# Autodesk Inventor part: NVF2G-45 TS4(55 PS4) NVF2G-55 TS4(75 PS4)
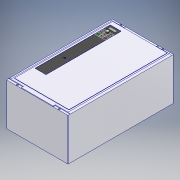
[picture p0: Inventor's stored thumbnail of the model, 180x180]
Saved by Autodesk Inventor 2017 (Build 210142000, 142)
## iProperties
Part Number: NVF2G-45 TS4(55 PS4) NVF2G-55 TS4(75 PS4)
Material: Типовые
Document SubType Name: Modeling
Designer: RSagdiev
Density: 1 g/cm^3
Appearance: По умолчанию
Mass: 52299.3 g
Surface Area: 17585.5 cm^2
Volume: 52299.3 cm^3
Author: RSagdiev
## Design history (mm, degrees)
sketch "Эскиз1"
  geometry: L1 (0, 0)-(44.679, 0) reference; L2 (0, 0)-(0, 56.035) reference; L3 (0, 0)-(603, 0); L4 (603, 0)-(603, 241.6); L5 (603, 241.6)-(0, 241.6); L6 (0, 241.6)-(0, 0)
  constraints: 12 end point, 3 horizontal, 2 parallel, 2 vertical, 1 perpendicular
  dimensions: "d0" = 603 distance of L5.end L4.end; "d1" = 241.6 distance of L4.end L3.end
extrude "Выдавливание1" new body sketch "Эскиз1" stored distance "d2" = 352; taper "d3" = 0 deg
sketch "Эскиз2"
  geometry: L1 (0, 0)-(0, 603) reference; L2 (352, 0)-(352, 603) reference; L3 (0, 603)-(85, 603); L4 (352, 603)-(352, 591); L5 (352, 0)-(267, 0); L6 (0, 0)-(0, 12); L7 (0, 603)-(352, 603) reference; L8 (0, 603)-(85, 603); L9 (85, 603)-(85, 591); L10 (85, 591)-(0, 591); L11 (0, 591)-(0, 603); L12 (352, 603)-(267, 603); L13 (267, 603)-(267, 591); L14 (267, 591)-(352, 591); L15 (352, 591)-(352, 603); L16 (0, 0)-(352, 0) reference; L17 (0, 0)-(85, 0); L18 (85, 0)-(85, 12); L19 (85, 12)-(0, 12); L20 (0, 12)-(0, 0); L21 (352, 0)-(267, 0); L22 (267, 0)-(267, 12); L23 (267, 12)-(352, 12); L24 (352, 12)-(352, 0); L25 (85, 603)-(267, 603); L26 (0, 591)-(0, 603); L27 (267, 603)-(352, 603); L28 (352, 591)-(352, 12); L29 (267, 0)-(85, 0); L30 (352, 12)-(352, 0); L31 (85, 0)-(0, 0); L32 (0, 12)-(0, 591); 1 further point
  constraints: 56 end point, 26 parallel, 13 perpendicular, 7 horizontal
  dimensions: "d4" = 85 distance of L9.end L10.end; "d5" = 12 distance of L3.end L9.end; "d6" = 85 distance of L4.end L13.end; "d7" = 12 distance of L13.end L12.end; "d8" = 85 distance of L6.end L18.end; "d9" = 12 distance of L18.end L17.end; "d10" = 85 distance of L22.end L23.end; "d11" = 12 distance of L5.end L22.end
extrude "Выдавливание2" new body sketch "Эскиз2" distance "d12" = 4; taper "d13" = 0 deg
chamfer "Фаска1" distance "d14" = 4; stored, may be unused: second distance "d15" = 2, angle "d16" = 45 deg
sketch "Эскиз3"
  geometry: L1 (332, 25)-(332, 587); L2 (20, 587)-(332, 587); L3 (20, 587)-(20, 25); L4 (20, 587)-(332, 587); L5 (20, 25)-(332, 25); L6 (85, 599)-(267, 599) reference; L7 (85, 0)-(267, 0) reference; L8 (0, 591)-(0, 12) reference; L9 (352, 12)-(352, 591) reference; 1 further point
  constraints: 11 end point, 2 perpendicular, 1 horizontal
  dimensions: "d160" = 12 distance between parallel lines of L4 L6; "d161" = 25 distance between parallel lines of L7 L5; "d162" = 20 distance between parallel lines of L8 L3 (derived); "d164" = 20 distance between parallel lines of L9 L1
extrude "Выдавливание3" new body sketch "Эскиз3" distance "d17" = 2; taper "d18" = 0 deg
sketch "Эскиз4"
  geometry: L1 (91, 563)-(32, 563); L2 (30, 561)-(30, 135); L3 (32, 133)-(91, 133); L4 (93, 135)-(93, 561); L5 (0, 603)-(352, 603) reference; L6 (0, 591)-(0, 12) reference; A1 r 2 centre (32, 561) between (32, 563) and (30, 561); A2 r 2 centre (91, 561) between (93, 561) and (91, 563); A3 r 2 centre (91, 135) between (91, 133) and (93, 135); A4 r 2 centre (32, 135) between (30, 135) and (32, 133); 6 further points
  constraints: 8 end point, 8 point on circle, 8 tangent, 6 point on line, 4 centre point, 3 equal radius, 2 parallel, 1 horizontal, 1 perpendicular
  dimensions: "d20" = 63 distance of point (93, 133) point (30, 133); "d21" = 430 distance of point (30, 133) point (30, 563); "d24" = 2 radius of A1; "d165" = 40 distance between parallel lines of L5 L1; "d166" = 30 distance between parallel lines of L6 L2
extrude "Выдавливание4" cut sketch "Эскиз4" distance "d25" = 0.6; taper "d26" = 0 deg
sketch "Эскиз5"
  geometry: L1 (0, 603)-(352, 603) reference; L2 (0, 0)-(0, 603) reference; L3 (352, 603)-(352, 0) reference; L4 (0, 0)-(352, 0) reference; C1 r 5 at (56, 597); C2 r 5 at (296, 597); C3 r 5 at (56, 6); C4 r 5 at (296, 6); 1 further point
  constraints: 4 centre point
  dimensions: "d27" = 10 diameter of C1; "d28" = 6 distance from line of C1.centre L1; "d30" = 10 diameter of C2; "d31" = 6 distance from line of C2.centre L1; "d33" = 10 diameter of C3; "d34" = 6 distance from line of L4 C3.centre; "d36" = 10 diameter of C4; "d38" = 6 distance from line of C4.centre L4; "d169" = 240 distance of C1.centre C2.centre; "d170" = 56 distance from line of L3 C2.centre; "d172" = 240 distance of C4.centre C3.centre (derived); "d173" = 56 distance from line of L3 C4.centre (derived); "d202" = 56 distance from line of L2 C1.centre (derived)
extrude "Выдавливание5" cut sketch "Эскиз5" stored distance "d39" = 0.6; taper "d40" = 0 deg
sketch "Эскиз6"
  geometry: L1 (30, 472)-(30, 528); L2 (91, 470)-(32, 470); L3 (93, 561)-(93, 528); L4 (32, 563)-(91, 563); L5 (30, 472)-(30, 561); L6 (30, 528)-(93, 528); L7 (93, 561)-(93, 528); L8 (30, 528)-(30, 561); L9 (93, 528)-(93, 472); L10 (43.5, 539)-(79.5, 539); L11 (81.5, 541)-(81.5, 551); L12 (79.5, 553)-(43.5, 553); L13 (41.5, 551)-(41.5, 541); L14 (41.5, 539)-(81.5, 553); L15 (81.5, 539)-(41.5, 553); L16 (61.5, 516.5)-(61.5, 481.857); L17 (53.25, 516.5)-(53.25, 481.857); L18 (69.75, 481.857)-(69.75, 516.5); L19 (47, 523)-(36, 523); L20 (35, 522)-(35, 511); L21 (36, 510)-(47, 510); L22 (48, 511)-(48, 522); L23 (48, 523)-(35, 510); L24 (35, 523)-(48, 510); L25 (81.5, 541)-(81.5, 476.5); L26 (41.5, 516.5)-(88.409, 516.5); L27 (39.654, 499.179)-(85.729, 499.179); L28 (39.654, 481.857)-(84.963, 481.857); L29 (88, 511)-(88, 522); L30 (76, 510)-(87, 510); L31 (88, 523)-(75, 510); L32 (75, 523)-(88, 510); L33 (75, 522)-(75, 511); L34 (87, 523)-(76, 523); L35 (88, 493.679)-(88, 504.679); L36 (76, 492.679)-(87, 492.679); L37 (88, 505.679)-(75, 492.679); L38 (75, 505.679)-(88, 492.679); L39 (75, 504.679)-(75, 493.679); L40 (87, 505.679)-(76, 505.679); L41 (88, 476.357)-(88, 487.357); L42 (76, 475.357)-(87, 475.357); L43 (88, 488.357)-(75, 475.357); L44 (75, 488.357)-(88, 475.357); L45 (75, 487.357)-(75, 476.357); L46 (87, 488.357)-(76, 488.357); L47 (48, 476.357)-(48, 487.357); L48 (36, 475.357)-(47, 475.357); L49 (48, 488.357)-(35, 475.357); L50 (35, 488.357)-(48, 475.357); L51 (35, 487.357)-(35, 476.357); L52 (47, 488.357)-(36, 488.357); L53 (48, 493.679)-(48, 504.679); L54 (36, 492.679)-(47, 492.679); L55 (48, 505.679)-(35, 492.679); L56 (35, 505.679)-(48, 492.679); L57 (35, 504.679)-(35, 493.679); L58 (47, 505.679)-(36, 505.679); L59 (91, 470)-(32, 470); L60 (0, 603)-(352, 603) reference; L61 (0, 589)-(0, 14); L62 (93, 528)-(93, 472); C1 r 6.5 at (61.5, 516.5); C2 r 6.5 at (61.5, 481.857); C3 r 6.5 at (61.5, 499.179); A1 r 2 centre (43.5, 551) between (43.5, 553) and (41.5, 551); A2 r 2 centre (79.5, 551) between (81.5, 551) and (79.5, 553); A3 r 2 centre (79.5, 541) between (79.5, 539) and (81.5, 541); A4 r 2 centre (43.5, 541) between (41.5, 541) and (43.5, 539); A5 r 8.25 centre (61.5, 516.5) between (69.75, 516.5) and (53.25, 516.5); A6 r 8.25 centre (61.5, 481.857) between (53.25, 481.857) and (69.75, 481.857); A7 r 1 centre (47, 522) between (48, 522) and (47, 523); A8 r 1 centre (47, 511) between (47, 510) and (48, 511); A9 r 1 centre (36, 511) between (35, 511) and (36, 510); A10 r 1 centre (36, 522) between (36, 523) and (35, 522); A11 r 1 centre (87, 511) between (87, 510) and (88, 511); A12 r 1 centre (87, 522) between (88, 522) and (87, 523); A13 r 1 centre (76, 522) between (76, 523) and (75, 522); A14 r 1 centre (76, 511) between (75, 511) and (76, 510); A15 r 1 centre (87, 493.679) between (87, 492.679) and (88, 493.679); A16 r 1 centre (87, 504.679) between (88, 504.679) and (87, 505.679); A17 r 1 centre (76, 504.679) between (76, 505.679) and (75, 504.679); A18 r 1 centre (76, 493.679) between (75, 493.679) and (76, 492.679); A19 r 1 centre (87, 476.357) between (87, 475.357) and (88, 476.357); A20 r 1 centre (87, 487.357) between (88, 487.357) and (87, 488.357); A21 r 1 centre (76, 487.357) between (76, 488.357) and (75, 487.357); A22 r 1 centre (76, 476.357) between (75, 476.357) and (76, 475.357); A23 r 1 centre (47, 476.357) between (47, 475.357) and (48, 476.357); A24 r 1 centre (47, 487.357) between (48, 487.357) and (47, 488.357); A25 r 1 centre (36, 487.357) between (36, 488.357) and (35, 487.357); A26 r 1 centre (36, 476.357) between (35, 476.357) and (36, 475.357); A27 r 1 centre (47, 493.679) between (47, 492.679) and (48, 493.679); A28 r 1 centre (47, 504.679) between (48, 504.679) and (47, 505.679); A29 r 1 centre (36, 504.679) between (36, 505.679) and (35, 504.679); A30 r 1 centre (36, 493.679) between (35, 493.679) and (36, 492.679); A31 r 2 centre (32, 561) between (32, 563) and (30, 561); A32 r 2 centre (91, 561) between (93, 561) and (91, 563); A33 r 2 centre (91, 472) between (91, 470) and (93, 472); A34 r 2 centre (32, 472) between (30, 472) and (32, 470); 15 further points
  constraints: 124 end point, 70 tangent, 68 point on circle, 67 point on line, 37 centre point, 21 equal radius, 15 midpoint, 15 parallel, 11 horizontal, 7 collinear, 7 perpendicular, 3 coincident, 2 vertical
  dimensions: "d43" = 35 distance between parallel lines of L4 L6; "d44" = 40 distance of L15.end L14.end; "d45" = 14 distance of L14.end L15.start; "d46" = 10 distance between parallel lines of L4 L12; "d47" = 2 radius of A1; "d48" = 11.5 distance between parallel lines of L8 L13; "d49" = 16.5 diameter of A6; "d50" = 31.5 distance between parallel lines of L1 L16; "d51" = 11.5 distance from line of L6 L16.start; "d52" = 11.85714 distance from line of L2 L16.end; "d53" = 13 diameter of C1; "d54" = 13 diameter of C2; "d55" = 13 diameter of C3; "d56" = 13 distance of L24.end L23.end; "d57" = 13 distance of L23.end L24.start; "d58" = 1 radius of A7 (derived); "d59" = 11.5 distance from line of L6 L26.start; "d60" = 11.5 distance from line of L5 L26.start; "d61" = 13 distance of L32.end L31.end; "d62" = 13 distance of L31.end L32.start; "d63" = 1 radius of A12 (derived); "d64" = 13 distance of L38.end L37.end; "d65" = 13 distance of L37.end L38.start; "d66" = 1 radius of A16 (derived); "d67" = 13 distance of L44.end L43.end; "d68" = 13 distance of L43.end L44.start; "d69" = 1 radius of A20 (derived); "d70" = 13 distance of L50.end L49.end; "d71" = 13 distance of L49.end L50.start; "d72" = 1 radius of A24 (derived); "d73" = 13 distance of L56.end L55.end; "d74" = 13 distance of L55.end L56.start; "d75" = 1 radius of A28 (derived); "d146" = 40 distance of point (81.5, 516.5) L26.start; "d147" = 4.32143 distance between parallel lines of L40 L30; "d148" = 4.32143 distance between parallel lines of L46 L36; "d149" = 93 distance between parallel lines of L2 L4; "d151" = 2 radius of A31; "d152" = 2 radius of A32; "d153" = 2 radius of A33; "d154" = 2 radius of A34; "d167" = 40 distance between parallel lines of L4 L60 (derived); "d168" = 30 distance between parallel lines of L61 L5 (derived)
extrude "Выдавливание6" new body sketch "Эскиз6" distance "d76" = 0.3; taper "d77" = 0 deg
extrude "Выдавливание7" new body sketch "Эскиз6" distance "d78" = 0.6; taper "d79" = 0 deg
sketch "Эскиз7"
  geometry: L1 (30, 528)-(93, 528) reference; L2 (30, 528)-(93, 528); L3 (93, 528)-(93, 528.1); L4 (93, 528.1)-(30, 528.1); L5 (30, 528.1)-(30, 528); 4 further points; 1 other entity
  constraints: 8 end point, 2 parallel, 1 horizontal, 1 perpendicular, 2 other
  dimensions: "d80" = 0.1 distance of L3.end L2.end
extrude "Выдавливание8" cut sketch "Эскиз7" distance "d81" = 0.3; taper "d82" = 0 deg
sketch "Эскиз8" dims "d91" = 10
  geometry: L1 (30, 528.1)-(93, 528.1) reference; C1 r 1 at (38, 533.1); C2 r 1 at (45.75, 533.1); C3 r 1 at (53.5, 533.1); C4 r 1 at (61.25, 533.1); C5 r 1 at (69, 533.1); C6 r 1 at (76.75, 533.1); C7 r 1 at (84.5, 533.1); 4 further points; 1 other entity
  constraints: 7 centre point, 1 horizontal, 13 other
  dimensions: "d83" = 2 diameter of C1; "d84" = 5 distance from line of C1.centre L1; "d85" = 8 dimension on C1.centre; "d88" = 7.75 distance of C1.centre C2.centre
extrude "Выдавливание9" join sketch "Эскиз8" distance "d93" = 0.3; taper "d94" = 0 deg
sketch "Эскиз9"
  geometry: C1 r 6.5 at (0, 0) reference; C2 r 7.5 at (0, 0); 1 further point
  constraints: 1 centre point, 1 coincident
  dimensions: "d95" = 15 diameter of C2
extrude "Выдавливание10" join sketch "Эскиз9" distance "d96" = 9.4; taper "d97" = -3 deg
sketch "Эскиз10"
  geometry: L1 (0, 7.331)-(0.619, 6.259); L2 (0.619, 6.259)-(-0.619, 6.259); L3 (-0.619, 6.259)-(0, 7.331); 2 further points
  constraints: 6 end point, 7 other
sketch "Эскиз11"
  geometry: L1 (0, 7.917)-(0.884, 6.386); L2 (0.884, 6.386)-(-0.884, 6.386); L3 (-0.884, 6.386)-(0, 7.917); 2 further points
  constraints: 6 end point, 7 other
feature "Лофт1" sketch "Эскиз10", "Эскиз11" dims "d98" = 0, "d99" = 90 deg, "d100" = 0, "d101" = 90 deg
sketch "Эскиз12"
  geometry: L1 (38.019, 518.873)-(44.239, 518.873); L2 (44.239, 518.873)-(44.239, 515.373); L3 (44.239, 515.373)-(38.019, 515.373); L4 (38.019, 515.373)-(38.019, 518.873); L5 (37.069, 501.774)-(45.924, 501.774); L6 (45.924, 501.774)-(45.924, 498.144); L7 (45.924, 498.144)-(37.069, 498.144); L8 (37.069, 498.144)-(37.069, 501.774); L9 (36.713, 484.438)-(46.07, 484.438); L10 (46.07, 484.438)-(46.07, 480.864); L11 (46.07, 480.864)-(36.713, 480.864); L12 (36.713, 480.864)-(36.713, 484.438); L13 (75.542, 484.438)-(87.094, 484.438); L14 (87.094, 484.438)-(87.094, 480.79); L15 (87.094, 480.79)-(75.542, 480.79); L16 (75.542, 480.79)-(75.542, 484.438); L17 (77.323, 501.655)-(85.517, 501.655); L18 (85.517, 501.655)-(85.517, 498.03); L19 (85.517, 498.03)-(77.323, 498.03); L20 (77.323, 498.03)-(77.323, 501.655); L21 (75.423, 518.992)-(88.473, 518.992); L22 (88.473, 518.992)-(88.473, 515.367); L23 (88.473, 515.367)-(75.423, 515.367); L24 (75.423, 515.367)-(75.423, 518.992); 1 further point
  constraints: 12 other
feature "Рельеф1" dims "d105" = 0.1, "d106" = 0
feature "Рельеф2" dims "d107" = 0.1, "d108" = 0
feature "Рельеф3" dims "d109" = 0.1, "d110" = 0
feature "Рельеф4" dims "d111" = 0.1, "d112" = 0
feature "Рельеф5" dims "d113" = 0.1, "d114" = 0
feature "Рельеф6" dims "d115" = 0.1, "d116" = 0
sketch "Эскиз13"
  geometry: L1 (-3.144, -2.347)-(-0.04, 3.728); L2 (-0.04, 3.728)-(3.298, -2.347); L3 (3.298, -2.347)-(2.096, -2.347); L4 (2.096, -2.347)-(-0.04, 1.541); L5 (-0.04, 1.541)-(-2.027, -2.347); L6 (-2.027, -2.347)-(-3.144, -2.347); L7 (-9.387, -8.657)-(8.031, -8.657); L8 (-3.144, -14.967)-(-0.04, -21.041); L9 (-0.04, -21.041)-(3.298, -14.967); L10 (3.298, -14.967)-(2.096, -14.967); L11 (2.096, -14.967)-(-0.04, -18.855); L12 (-0.04, -18.855)-(-2.027, -14.967); L13 (-2.027, -14.967)-(-3.144, -14.967); 1 further point
  constraints: 26 end point, 6 symmetric about line, 2 horizontal, 2 parallel, 2 point on line, 1 collinear
feature "Рельеф7" dims "d117" = 0.1, "d118" = 0
feature "Рельеф8" dims "d119" = 0.1, "d120" = 0
sketch "Эскиз14"
  geometry: L1 (62.079, 278.98)-(70.375, 264.61); L2 (70.375, 264.61)-(53.782, 264.61); L3 (53.782, 264.61)-(62.079, 278.98); L4 (68.948, 265.434)-(62.079, 277.332); L5 (62.079, 277.332)-(55.209, 265.434); L6 (55.209, 265.434)-(68.948, 265.434); L7 (61.252, 273.665)-(60.311, 269.855); L8 (60.311, 269.855)-(62.732, 270.025); L9 (62.732, 270.025)-(61.691, 267.709); L10 (61.691, 267.709)-(60.742, 268.135); L11 (60.742, 268.135)-(60.898, 265.905); L12 (60.898, 265.905)-(63.368, 266.954); L13 (63.368, 266.954)-(62.687, 267.261); L14 (62.687, 267.261)-(64.617, 270.896); L15 (64.617, 270.896)-(61.462, 270.713); L16 (61.462, 270.713)-(63.028, 273.665); L17 (63.028, 273.665)-(61.252, 273.665); 2 further points
  constraints: 34 end point, 2 perpendicular, 2 point on line, 1 parallel, 9 other
extrude "Выдавливание11" cut sketch "Эскиз14" distance "d121" = 0.8; taper "d122" = 0 deg
extrude "Выдавливание12" join sketch "Эскиз14" stored distance "d123" = 0.05; taper "d124" = 0 deg
sketch "Эскиз15"
  geometry: L1 (32.937, 537.243)-(56.472, 537.243); L2 (56.472, 537.243)-(56.472, 534.81); L3 (56.472, 534.81)-(32.937, 534.81); L4 (32.937, 534.81)-(32.937, 537.243); L5 (58.162, 536.617)-(88.881, 536.617); L6 (88.881, 536.617)-(88.881, 532.704); L7 (88.881, 532.704)-(58.162, 532.704); L8 (58.162, 532.704)-(58.162, 536.617); L9 (30, 528.1)-(93, 528.1) reference; C1 r 1 at (38, 533.1) reference; 7 further points; 2 other entities
  constraints: 6 other
  dimensions: "d155" = 0.71019 distance edge to line of C1 L3; "d156" = 2.93695 dimension on L4; "d157" = 4.60387 distance between parallel lines of L9 L7; "d158" = 4.11868 dimension on L6
feature "Рельеф9" sketch "Эскиз15" dims "d125" = 0.1, "d126" = 0
sketch "Эскиз17"
  geometry: L1 (54.534, 359)-(54.534, 352.001); L2 (54.534, 352.001)-(52.465, 352.001); L3 (52.465, 352.001)-(52.465, 359); L4 (52.465, 359)-(54.534, 359); 1 further point
  constraints: 2 other
feature "Рельеф10" sketch "Эскиз17" dims "d144" = 0.1, "d145" = 0
sketch "Эскиз19" dims "d179" = 10
  geometry: L1 (113.24, 333.958)-(134.375, 351.485); L2 (114.525, 332.409)-(135.66, 349.935); L3 (133.09, 353.034)-(111.955, 335.508); L4 (241.6, 591)-(241.6, 12) reference; L5 (113.24, 323.958)-(134.375, 341.485); L6 (114.525, 322.409)-(135.66, 339.935); L7 (133.09, 343.034)-(111.955, 325.508); L8 (113.24, 313.958)-(134.375, 331.485); L9 (114.525, 312.409)-(135.66, 329.935); L10 (133.09, 333.034)-(111.955, 315.508); L11 (113.24, 303.958)-(134.375, 321.485); L12 (114.525, 302.409)-(135.66, 319.935); L13 (133.09, 323.034)-(111.955, 305.508); L14 (113.24, 293.958)-(134.375, 311.485); L15 (114.525, 292.409)-(135.66, 309.935); L16 (133.09, 313.034)-(111.955, 295.508); L17 (113.24, 283.958)-(134.375, 301.485); L18 (114.525, 282.409)-(135.66, 299.935); L19 (133.09, 303.034)-(111.955, 285.508); L20 (113.24, 273.958)-(134.375, 291.485); L21 (114.525, 272.409)-(135.66, 289.935); L22 (133.09, 293.034)-(111.955, 275.508); L23 (113.24, 263.958)-(134.375, 281.485); L24 (114.525, 262.409)-(135.66, 279.935); L25 (133.09, 283.034)-(111.955, 265.508); L26 (113.24, 253.958)-(134.375, 271.485); L27 (114.525, 252.409)-(135.66, 269.935); L28 (133.09, 273.034)-(111.955, 255.508); L29 (113.24, 243.958)-(134.375, 261.485); L30 (114.525, 242.409)-(135.66, 259.935); L31 (133.09, 263.034)-(111.955, 245.508); A1 r 2.013 centre (113.24, 333.958) between (111.955, 335.508) and (114.525, 332.409); A2 r 2.013 centre (134.375, 351.485) between (135.66, 349.935) and (133.09, 353.034); A3 r 2.013 centre (113.24, 323.958) between (111.955, 325.508) and (114.525, 322.409); A4 r 2.013 centre (134.375, 341.485) between (135.66, 339.935) and (133.09, 343.034); A5 r 2.013 centre (113.24, 313.958) between (111.955, 315.508) and (114.525, 312.409); A6 r 2.013 centre (134.375, 331.485) between (135.66, 329.935) and (133.09, 333.034); A7 r 2.013 centre (113.24, 303.958) between (111.955, 305.508) and (114.525, 302.409); A8 r 2.013 centre (134.375, 321.485) between (135.66, 319.935) and (133.09, 323.034); A9 r 2.013 centre (113.24, 293.958) between (111.955, 295.508) and (114.525, 292.409); A10 r 2.013 centre (134.375, 311.485) between (135.66, 309.935) and (133.09, 313.034); A11 r 2.013 centre (113.24, 283.958) between (111.955, 285.508) and (114.525, 282.409); A12 r 2.013 centre (134.375, 301.485) between (135.66, 299.935) and (133.09, 303.034); A13 r 2.013 centre (113.24, 273.958) between (111.955, 275.508) and (114.525, 272.409); A14 r 2.013 centre (134.375, 291.485) between (135.66, 289.935) and (133.09, 293.034); A15 r 2.013 centre (113.24, 263.958) between (111.955, 265.508) and (114.525, 262.409); A16 r 2.013 centre (134.375, 281.485) between (135.66, 279.935) and (133.09, 283.034); A17 r 2.013 centre (113.24, 253.958) between (111.955, 255.508) and (114.525, 252.409); A18 r 2.013 centre (134.375, 271.485) between (135.66, 269.935) and (133.09, 273.034); A19 r 2.013 centre (113.24, 243.958) between (111.955, 245.508) and (114.525, 242.409); A20 r 2.013 centre (134.375, 261.485) between (135.66, 259.935) and (133.09, 263.034); 13 further points
  constraints: 80 end point, 40 point on circle, 20 centre point, 4 tangent, 1 midpoint, 1 parallel, 1 vertical, 108 other
  dimensions: "d176" = 10 distance of L2.start L6.start
extrude "Выдавливание14" cut sketch "Эскиз19" distance "d181" = 10; taper "d182" = 0 deg
sketch "Эскиз20" dims "d191" = 10, "d198" = 10
  geometry: L1 (241.6, 2)-(0, 2) reference; L2 (0, 603)-(0, 0) reference; C1 r 2 at (15, 132); C2 r 2 at (20, 132); C3 r 2 at (25, 132); C4 r 2 at (30, 132); C5 r 2 at (35, 132); C6 r 2 at (40, 132); C7 r 2 at (45, 132); C8 r 2 at (50, 132); C9 r 2 at (55, 132); C10 r 2 at (60, 132); C11 r 2 at (65, 132); C12 r 2 at (70, 132); C13 r 2 at (70, 127); C14 r 2 at (65, 127); C15 r 2 at (60, 127); C16 r 2 at (55, 127); C17 r 2 at (15, 127); C18 r 2 at (20, 127); C19 r 2 at (25, 127); C20 r 2 at (30, 127); C21 r 2 at (35, 127); C22 r 2 at (40, 127); C23 r 2 at (45, 127); C24 r 2 at (50, 127); C25 r 2 at (70, 122); C26 r 2 at (65, 122); C27 r 2 at (60, 122); C28 r 2 at (55, 122); C29 r 2 at (15, 122); C30 r 2 at (20, 122); C31 r 2 at (25, 122); C32 r 2 at (30, 122); C33 r 2 at (35, 122); C34 r 2 at (40, 122); C35 r 2 at (45, 122); C36 r 2 at (50, 122); C37 r 2 at (70, 117); C38 r 2 at (65, 117); C39 r 2 at (60, 117); C40 r 2 at (55, 117); C41 r 2 at (15, 117); C42 r 2 at (20, 117); C43 r 2 at (25, 117); C44 r 2 at (30, 117); C45 r 2 at (35, 117); C46 r 2 at (40, 117); C47 r 2 at (45, 117); C48 r 2 at (50, 117); C49 r 2 at (70, 112); C50 r 2 at (65, 112); C51 r 2 at (60, 112); C52 r 2 at (55, 112); C53 r 2 at (15, 112); C54 r 2 at (20, 112); C55 r 2 at (25, 112); C56 r 2 at (30, 112); C57 r 2 at (35, 112); C58 r 2 at (40, 112); C59 r 2 at (45, 112); C60 r 2 at (50, 112); C61 r 2 at (70, 107); C62 r 2 at (65, 107); C63 r 2 at (60, 107); C64 r 2 at (55, 107)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; 1 further point
  constraints: 240 centre point, 1 horizontal, 1 vertical, 478 other
  dimensions: "d183" = 4 diameter of C1; "d184" = 15 distance from line of L2 C1.centre; "d185" = 130 distance from line of L1 C1.centre; "d188" = 5 distance of C1.centre C2.centre; "d195" = 5 distance of C12.centre C13.centre
extrude "Выдавливание15" cut sketch "Эскиз20" distance "d200" = 15; taper "d201" = 0 deg
fillet "Сопряжение3" dims "d203" = 20
fillet "Сопряжение4" dims "d204" = 2
node "Твердое тело1"
pattern_circular "Круговой массив1" dims angle "d103" = 360 deg
node "Твердое тело2"
node "Твердое тело3"
node "Твердое тело4"
node "Твердое тело5"
